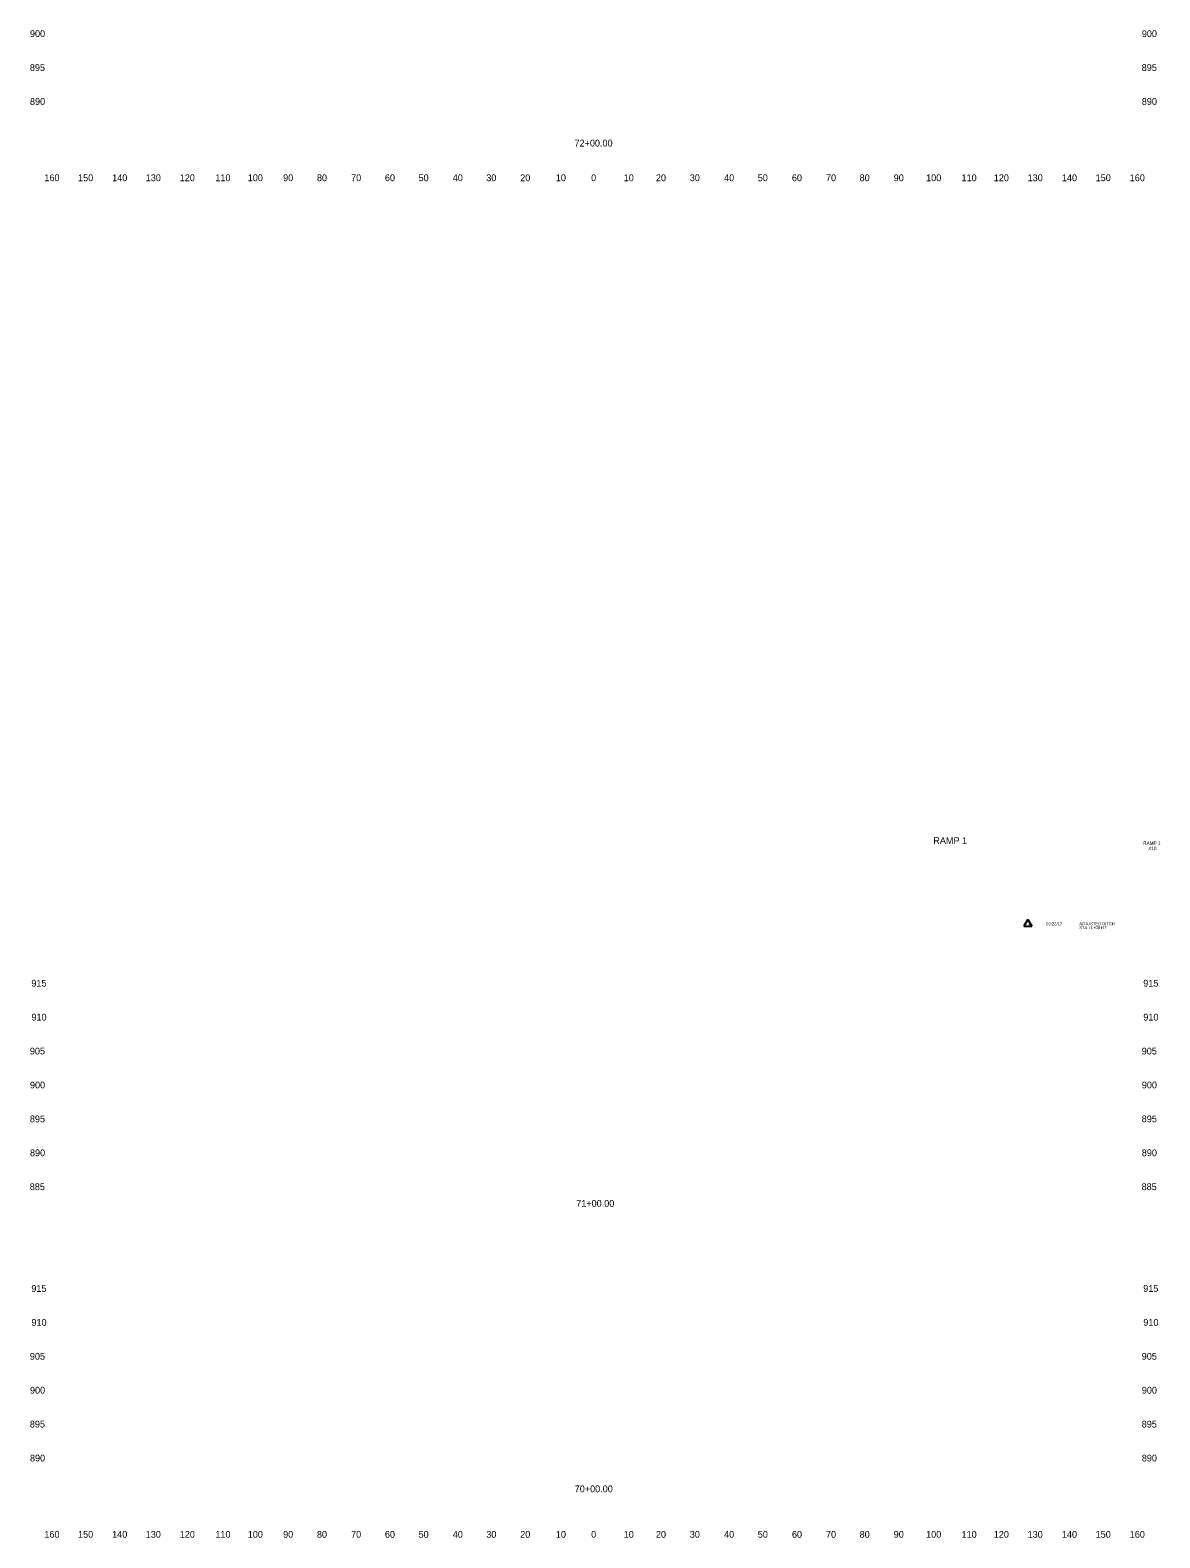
# Model space of a CAD drawing. Extents: x 4994 to 7869, y 4997 to 8804.
# Drawn here: x 5508.9 to 5842, y 6997.5 to 7442 of the extents above; entities that cross this region are included whole.
import ezdxf

# ---------------------------------------------------------------- set-up
doc = ezdxf.new("R2010")
doc.units = 0
for name, color, linetype in [('RD_SHT_ID', 7, 'Continuous'), ('RD_SHT_TX', 7, 'Continuous'), ('RD_XS_TX_Offset', 7, 'Continuous'), ('RD_XS_TX_Station', 7, 'Continuous')]:
    doc.layers.add(name, color=color, linetype=linetype)

msp = doc.modelspace()

# ---------------------------------------------------------------- linework, layer by layer
at = {"layer": 'RD_SHT_TX'}
for p, q in [((5803.05, 7179.83), (5801.91, 7177.8)), ((5803.05, 7179.83), (5804.19, 7177.8)), ((5801.91, 7177.8), (5804.19, 7177.8))]:
    msp.add_line(p, q, dxfattribs=at)

# ---------------------------------------------------------------- texts
at = {"layer": 'RD_SHT_ID'}
for s, height, p in [('RAMP 1', 2, (5775.19, 7202.06)), ('RAMP 1', 1, (5837.06, 7201.8)), ('X16', 1, (5838.55, 7200.3))]:
    msp.add_text(s, height=height, dxfattribs=at).set_placement(p)
at = {"layer": 'RD_SHT_TX'}
for s, p in [('1', (5803.05, 7178.13)), ('02/22/17', (5808.44, 7178.09)), ('ADJUSTED DITCH', (5818.22, 7178.12)), ('STA 71+00 RT', (5818.22, 7176.95))]:
    msp.add_text(s, height=0.88, dxfattribs=at).set_placement(p)
at = {"layer": 'RD_XS_TX_Offset'}
for s, p in [('900', (5508.86, 7440)), ('900', (5836.66, 7440)), ('895', (5508.83, 7430)), ('895', (5836.63, 7430)), ('890', (5508.86, 7420)), ('890', (5836.66, 7420)), ('160', (5513.1, 7397.5)), ('150', (5523.04, 7397.5)), ('140', (5533.1, 7397.5)), ('130', (5542.99, 7397.5)), ('120', (5553.01, 7397.5)), ('110', (5563.51, 7397.5)), ('100', (5573.07, 7397.5)), ('90', (5583.5, 7397.5)), ('80', (5593.46, 7397.5)), ('70', (5603.54, 7397.5)), ('60', (5613.5, 7397.5)), ('50', (5623.43, 7397.5)), ('40', (5633.5, 7397.5)), ('30', (5643.39, 7397.5)), ('20', (5653.4, 7397.5)), ('10', (5663.91, 7397.5)), ('0', (5674.3, 7397.5)), ('0', (5674.3, 7397.5)), ('10', (5683.91, 7397.5)), ('20', (5693.4, 7397.5)), ('30', (5703.39, 7397.5)), ('40', (5713.5, 7397.5)), ('50', (5723.43, 7397.5)), ('60', (5733.5, 7397.5)), ('70', (5743.54, 7397.5)), ('80', (5753.46, 7397.5)), ('90', (5763.5, 7397.5)), ('100', (5773.07, 7397.5)), ('110', (5783.51, 7397.5)), ('120', (5793.01, 7397.5)), ('130', (5802.99, 7397.5)), ('140', (5813.1, 7397.5)), ('150', (5823.04, 7397.5)), ('160', (5833.1, 7397.5)), ('915', (5509.27, 7160)), ('915', (5837.07, 7160)), ('910', (5509.3, 7150)), ('910', (5837.1, 7150)), ('905', (5508.83, 7140)), ('905', (5836.63, 7140)), ('900', (5508.86, 7130)), ('900', (5836.66, 7130)), ('895', (5508.83, 7120)), ('895', (5836.63, 7120)), ('890', (5508.86, 7110)), ('890', (5836.66, 7110)), ('885', (5508.8, 7100)), ('885', (5836.6, 7100)), ('915', (5509.27, 7070)), ('915', (5837.07, 7070)), ('910', (5509.3, 7060)), ('910', (5837.1, 7060)), ('905', (5508.83, 7050)), ('905', (5836.63, 7050)), ('900', (5508.86, 7040)), ('900', (5836.66, 7040)), ('895', (5508.83, 7030)), ('895', (5836.63, 7030)), ('890', (5508.86, 7020)), ('890', (5836.66, 7020)), ('160', (5513.1, 6997.5)), ('150', (5523.04, 6997.5)), ('140', (5533.1, 6997.5)), ('130', (5542.99, 6997.5)), ('120', (5553.01, 6997.5)), ('110', (5563.51, 6997.5)), ('100', (5573.07, 6997.5)), ('90', (5583.5, 6997.5)), ('80', (5593.46, 6997.5)), ('70', (5603.54, 6997.5)), ('60', (5613.5, 6997.5)), ('50', (5623.43, 6997.5)), ('40', (5633.5, 6997.5)), ('30', (5643.39, 6997.5)), ('20', (5653.4, 6997.5)), ('10', (5663.91, 6997.5)), ('0', (5674.3, 6997.5)), ('0', (5674.3, 6997.5)), ('10', (5683.91, 6997.5)), ('20', (5693.4, 6997.5)), ('30', (5703.39, 6997.5)), ('40', (5713.5, 6997.5)), ('50', (5723.43, 6997.5)), ('60', (5733.5, 6997.5)), ('70', (5743.54, 6997.5)), ('80', (5753.46, 6997.5)), ('90', (5763.5, 6997.5)), ('100', (5773.07, 6997.5)), ('110', (5783.51, 6997.5)), ('120', (5793.01, 6997.5)), ('130', (5802.99, 6997.5)), ('140', (5813.1, 6997.5)), ('150', (5823.04, 6997.5)), ('160', (5833.1, 6997.5))]:
    msp.add_text(s, height=2, dxfattribs=at).set_placement(p)
at = {"layer": 'RD_XS_TX_Station'}
for s, p in [('72+00.00', (5669.4, 7407.72)), ('71+00.00', (5669.91, 7095.08)), ('70+00.00', (5669.46, 7010.92))]:
    msp.add_text(s, height=2, dxfattribs=at).set_placement(p)

doc.saveas('drawing.dxf')
